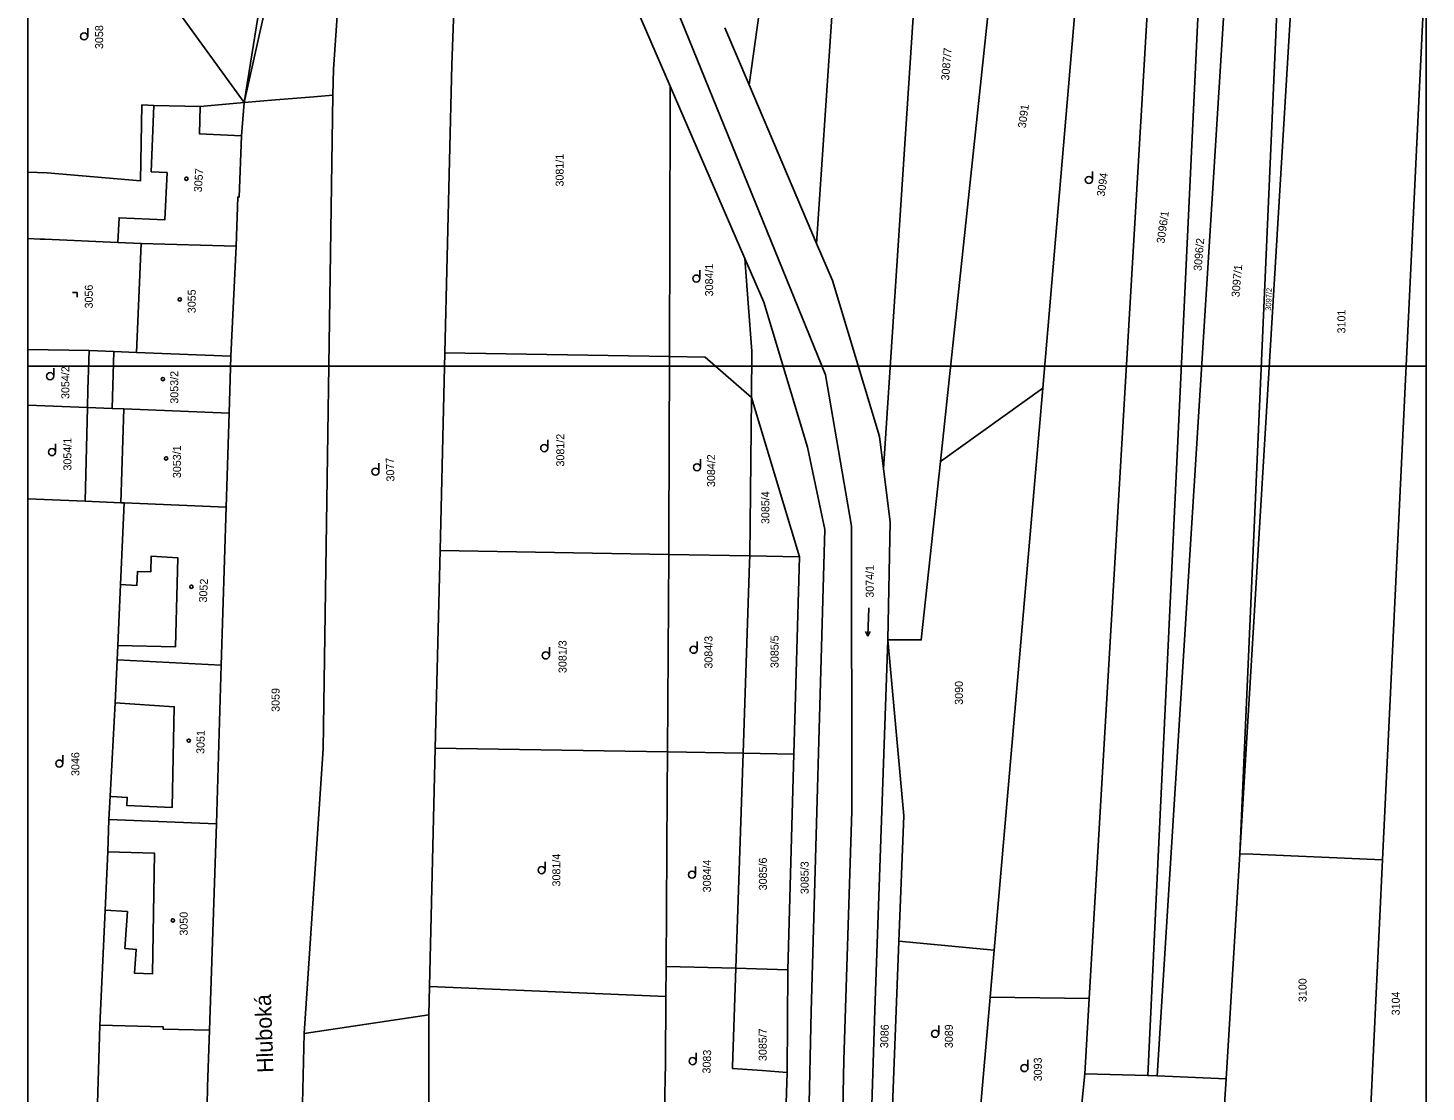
# Model space of a CAD drawing. Extents: x -534410 to -534262, y -1190162 to -1189584.
# Drawn here: x -534410.1 to -534261.6, y -1190081.5 to -1189968.6 of the extents above; entities that cross this region are included whole.
import ezdxf

# ---------------------------------------------------------------- set-up
doc = ezdxf.new("R2010")
doc.units = 0
for name, color, linetype in [('_KN_Povodí_Moravy', 7, 'Continuous'), ('_N_osa', 7, 'Continuous'), ('_rámeček', 7, 'Continuous'), ('_rámeček_mřížka', 7, 'Continuous'), ('_tenka', 7, 'Continuous'), ('Hranice parcel', 7, 'Continuous'), ('Parcelní čísla', 7, 'Continuous'), ('Polygon budovy', 7, 'Continuous'), ('Pop  PČ popisy', 7, 'Continuous'), ('Značky budov', 7, 'Continuous'), ('Značky kultur', 7, 'Continuous')]:
    doc.layers.add(name, color=color, linetype=linetype)

msp = doc.modelspace()

# ---------------------------------------------------------------- linework, layer by layer
at = {"layer": '_KN_Povodí_Moravy'}
for p, q in [((-534351.04, -1189953.66), (-534341.9, -1189974.75)), ((-534333.52, -1189974.6), (-534336.09, -1189968.55)), ((-534341.9, -1189974.75), (-534333.99, -1189993.03)), ((-534326.36, -1189991.44), (-534333.52, -1189974.6))]:
    msp.add_line(p, q, dxfattribs=at)
for points in [[(-534319.25, -1190015.38), (-534319.67, -1190011.96), (-534324.68, -1189995.39), (-534326.36, -1189991.44)], [(-534333.99, -1189993.03), (-534331.98, -1189997.67), (-534327.34, -1190013.08), (-534325.48, -1190021.81), (-534326.93, -1190073), (-534328.13, -1190128.3), (-534328.71, -1190131.86)], [(-534318.8, -1190033.53), (-534318.55, -1190021), (-534319.25, -1190015.38)], [(-534322.11, -1190134.26), (-534321.95, -1190128.7), (-534320.16, -1190072.85), (-534318.8, -1190033.53)]]:
    msp.add_lwpolyline(points, dxfattribs=at)
at = {"layer": '_N_osa'}
msp.add_lwpolyline([(-534327.36, -1190134.6), (-534324.33, -1190120.41), (-534323.46, -1190078.16), (-534322.63, -1190051.74), (-534322.66, -1190021.45), (-534325.42, -1190005.39), (-534346.1, -1189954.57), (-534347.89, -1189950.33)], dxfattribs=at)
at = {"layer": '_rámeček'}
msp.add_line((-534410.13, -1189584.47), (-534410.13, -1190161.97), dxfattribs=at)
msp.add_lwpolyline([(-534410.13, -1190161.97), (-534261.63, -1190161.97), (-534261.63, -1189584.47)], dxfattribs=at)
for points in [[(-534410.13, -1189899.47), (-534261.63, -1189899.47), (-534261.63, -1190004.47), (-534410.13, -1190004.47)], [(-534410.13, -1190004.47), (-534261.63, -1190004.47), (-534261.63, -1190109.47), (-534410.13, -1190109.47)]]:
    msp.add_lwpolyline(points, close=True, dxfattribs=at)
at = {"layer": '_rámeček_mřížka'}
for p, q in [((-534410.13, -1189584.47), (-534410.13, -1190161.97)), ((-534407.13, -1190004.47), (-534410.13, -1190004.47)), ((-534264.63, -1190004.47), (-534261.63, -1190004.47))]:
    msp.add_line(p, q, dxfattribs=at)
msp.add_lwpolyline([(-534410.13, -1190161.97), (-534261.63, -1190161.97), (-534261.63, -1189584.47)], dxfattribs=at)
at = {"layer": '_tenka'}
for p, q in [((-534320.8, -1190030.14), (-534320.93, -1190033.14)), ((-534320.93, -1190033.14), (-534321.16, -1190032.64)), ((-534320.93, -1190033.14), (-534320.66, -1190032.66))]:
    msp.add_line(p, q, dxfattribs=at)
at = {"layer": 'Hranice parcel'}
for p, q in [((-534326.36, -1189991.44), (-534323.33, -1189946.13)), ((-534319.25, -1190015.38), (-534314.72, -1189945.99)), ((-534313.21, -1190014.59), (-534305.87, -1189945.8)), ((-534302.34, -1190006.82), (-534297.16, -1189946.38)), ((-534290.08, -1189946.94), (-534297.41, -1190071.61)), ((-534291.17, -1190079.8), (-534284.92, -1189947.42)), ((-534290.2, -1190079.83), (-534281.9, -1189947.69)), ((-534281.42, -1190056.27), (-534276.65, -1189947.93)), ((-534281.42, -1190056.27), (-534274.89, -1189948.14)), ((-534351.04, -1189953.66), (-534341.9, -1189974.75)), ((-534261.63, -1189960.81), (-534266.24, -1190056.9)), ((-534396.36, -1189963.8), (-534387.17, -1189976.47)), ((-534384.28, -1189963.65), (-534387.17, -1189976.47)), ((-534387.17, -1189976.47), (-534385.09, -1189963.71)), ((-534333.52, -1189974.6), (-534336.09, -1189968.55)), ((-534341.9, -1189974.75), (-534333.99, -1189993.03)), ((-534326.36, -1189991.44), (-534333.52, -1189974.6)), ((-534388.01, -1189991.75), (-534387.85, -1189986.52)), ((-534398.09, -1189991.44), (-534398.61, -1190003.03)), ((-534388.01, -1189991.75), (-534398.09, -1189991.44)), ((-534388.57, -1190003.43), (-534388.01, -1189991.75)), ((-534410.13, -1190002.69), (-534403.61, -1190002.82)), ((-534398.61, -1190003.03), (-534388.57, -1190003.43)), ((-534366.35, -1190024.04), (-534365.84, -1190003.05)), ((-534365.84, -1190003.05), (-534341.99, -1190003.45)), ((-534388.57, -1190003.43), (-534388.75, -1190009.46)), ((-534302.34, -1190006.82), (-534313.21, -1190014.59)), ((-534307.49, -1190066.49), (-534302.34, -1190006.82)), ((-534403.8, -1190008.85), (-534410.13, -1190008.6)), ((-534403.8, -1190008.85), (-534404.06, -1190018.82)), ((-534333.46, -1190024.63), (-534333.29, -1190007.81)), ((-534333.29, -1190007.81), (-534328.17, -1190024.72)), ((-534388.75, -1190009.46), (-534389.06, -1190019.44)), ((-534404.06, -1190018.82), (-534410.13, -1190018.57)), ((-534389.06, -1190019.44), (-534399.91, -1190018.99)), ((-534389.59, -1190036.21), (-534389.06, -1190019.44)), ((-534366.87, -1190045.04), (-534366.35, -1190024.04)), ((-534366.35, -1190024.04), (-534342.06, -1190024.47)), ((-534342.19, -1190045.44), (-534342.06, -1190024.47)), ((-534342.06, -1190024.47), (-534333.46, -1190024.63)), ((-534333.46, -1190024.63), (-534328.17, -1190024.72)), ((-534328.17, -1190024.72), (-534328.79, -1190045.66)), ((-534389.59, -1190036.21), (-534400.65, -1190035.66)), ((-534390.11, -1190053.08), (-534389.59, -1190036.21)), ((-534367.49, -1190070.35), (-534366.87, -1190045.04)), ((-534366.87, -1190045.04), (-534342.19, -1190045.44)), ((-534342.19, -1190045.44), (-534334.16, -1190045.57)), ((-534334.93, -1190068.41), (-534334.16, -1190045.57)), ((-534334.16, -1190045.57), (-534328.79, -1190045.66)), ((-534328.79, -1190045.66), (-534329.41, -1190068.56)), ((-534390.11, -1190053.08), (-534401.52, -1190052.62)), ((-534390.83, -1190074.99), (-534390.11, -1190053.08)), ((-534282.87, -1190080.13), (-534281.42, -1190056.27)), ((-534266.24, -1190056.9), (-534267.52, -1190083.79)), ((-534318.39, -1190085.1), (-534317.63, -1190065.52)), ((-534307.49, -1190066.49), (-534317.63, -1190065.52)), ((-534307.92, -1190071.47), (-534307.49, -1190066.49)), ((-534342.35, -1190068.22), (-534342.37, -1190071.42)), ((-534334.93, -1190068.41), (-534342.35, -1190068.22)), ((-534334.93, -1190068.41), (-534329.41, -1190068.56)), ((-534329.41, -1190068.56), (-534329.49, -1190079.46)), ((-534367.56, -1190073.35), (-534367.49, -1190070.35)), ((-534342.37, -1190071.42), (-534367.49, -1190070.35)), ((-534309.15, -1190085.72), (-534307.92, -1190071.47)), ((-534297.41, -1190071.61), (-534307.92, -1190071.47)), ((-534297.88, -1190079.61), (-534297.41, -1190071.61)), ((-534367.56, -1190073.35), (-534380.79, -1190075.34)), ((-534329.74, -1190087.07), (-534329.49, -1190079.46)), ((-534298.53, -1190086.06), (-534297.88, -1190079.61)), ((-534291.17, -1190079.8), (-534297.88, -1190079.61)), ((-534290.2, -1190079.83), (-534291.17, -1190079.8)), ((-534282.87, -1190080.13), (-534290.2, -1190079.83)), ((-534283.03, -1190082.87), (-534282.87, -1190080.13))]:
    msp.add_line(p, q, dxfattribs=at)
for points in [[(-534333.52, -1189974.6), (-534331.59, -1189960.61), (-534330.81, -1189946.26)], [(-534365.84, -1190003.05), (-534365.09, -1189972.48), (-534364.31, -1189951.16)], [(-534377.74, -1189975.71), (-534377.67, -1189972.94), (-534376.87, -1189961.07), (-534375.31, -1189953.34)], [(-534341.99, -1190003.45), (-534341.91, -1189977.12), (-534341.9, -1189974.75)], [(-534387.17, -1189976.47), (-534391.84, -1189976.92), (-534396.75, -1189976.78), (-534398.02, -1189976.74), (-534398.19, -1189984.8), (-534408.09, -1189983.96), (-534410.13, -1189983.88)], [(-534387.85, -1189986.52), (-534387.71, -1189986.52), (-534387.44, -1189980.01), (-534387.17, -1189976.47)], [(-534387.17, -1189976.47), (-534383.85, -1189976.2), (-534379.76, -1189975.87), (-534377.74, -1189975.71)], [(-534380.79, -1190075.34), (-534378.76, -1190045.09), (-534377.74, -1189975.71)], [(-534398.09, -1189991.44), (-534400.58, -1189991.34), (-534408.35, -1189991), (-534408.84, -1189990.98), (-534410.13, -1189990.91)], [(-534319.25, -1190015.38), (-534319.67, -1190011.96), (-534324.68, -1189995.39), (-534326.36, -1189991.44)], [(-534333.29, -1190007.81), (-534333.24, -1190002.9), (-534333.62, -1189997.8), (-534333.99, -1189993.03)], [(-534333.99, -1189993.03), (-534331.98, -1189997.67), (-534327.34, -1190013.08), (-534325.48, -1190021.81), (-534326.93, -1190073), (-534328.13, -1190128.3), (-534328.71, -1190131.86)], [(-534403.61, -1190002.82), (-534403.75, -1190006.97), (-534403.8, -1190008.85)], [(-534403.61, -1190002.82), (-534400.99, -1190002.93), (-534398.61, -1190003.03)], [(-534342.06, -1190024.47), (-534342.05, -1190022.37), (-534341.99, -1190003.45)], [(-534341.99, -1190003.45), (-534338.18, -1190003.51), (-534333.29, -1190007.81)], [(-534388.75, -1190009.46), (-534399.94, -1190009.01), (-534401.17, -1190008.96), (-534403.8, -1190008.85)], [(-534313.21, -1190014.59), (-534315.24, -1190033.54), (-534318.8, -1190033.53)], [(-534318.8, -1190033.53), (-534318.55, -1190021), (-534319.25, -1190015.38)], [(-534399.91, -1190018.99), (-534400.27, -1190018.98), (-534404.06, -1190018.82)], [(-534400.65, -1190035.66), (-534400.58, -1190034.14), (-534400.29, -1190027.66), (-534399.91, -1190018.99)], [(-534334.16, -1190045.57), (-534333.47, -1190025.37), (-534333.46, -1190024.63)], [(-534322.11, -1190134.26), (-534321.95, -1190128.7), (-534320.16, -1190072.85), (-534318.8, -1190033.53)], [(-534317.63, -1190065.52), (-534317.11, -1190052.22), (-534318.8, -1190033.53)], [(-534401.52, -1190052.62), (-534401.39, -1190050.15), (-534400.88, -1190040.21), (-534400.65, -1190035.66)], [(-534342.35, -1190068.22), (-534342.22, -1190049.76), (-534342.19, -1190045.44)], [(-534402.48, -1190074.44), (-534401.92, -1190062.24), (-534401.64, -1190056.04), (-534401.52, -1190052.62)], [(-534266.24, -1190056.9), (-534280.03, -1190056.3), (-534281.42, -1190056.27)], [(-534329.49, -1190079.46), (-534332.14, -1190079.27), (-534335.3, -1190079.04), (-534335.29, -1190078.85), (-534334.93, -1190068.41)], [(-534342.57, -1190087.3), (-534342.5, -1190083.48), (-534342.42, -1190078.52), (-534342.37, -1190071.42)], [(-534402.81, -1190084.96), (-534402.74, -1190082.76), (-534402.48, -1190074.44)], [(-534390.83, -1190074.99), (-534395.76, -1190074.86), (-534395.76, -1190074.64), (-534402.48, -1190074.44)], [(-534367.47, -1190102.26), (-534367.55, -1190076.15), (-534367.56, -1190073.35)], [(-534391.6, -1190100.55), (-534391.1, -1190082.99), (-534391.04, -1190081), (-534390.83, -1190074.99)], [(-534381.06, -1190105.11), (-534381.43, -1190102.09), (-534380.79, -1190075.34)]]:
    msp.add_lwpolyline(points, dxfattribs=at)
at = {"layer": 'Polygon budovy'}
for points in [[(-534397.05, -1189983.85), (-534395.35, -1189983.92), (-534395.59, -1189988.94), (-534400.44, -1189988.72), (-534400.58, -1189991.34), (-534398.09, -1189991.44), (-534388.01, -1189991.75), (-534387.85, -1189986.52), (-534387.71, -1189986.52), (-534387.44, -1189980.01), (-534391.9, -1189979.81), (-534391.84, -1189976.92), (-534396.75, -1189976.78)], [(-534398.61, -1190003.03), (-534388.57, -1190003.43), (-534388.01, -1189991.75), (-534398.09, -1189991.44)], [(-534400.99, -1190002.93), (-534401.17, -1190008.96), (-534399.94, -1190009.01), (-534388.75, -1190009.46), (-534388.57, -1190003.43), (-534398.61, -1190003.03)], [(-534399.91, -1190018.99), (-534389.06, -1190019.44), (-534388.75, -1190009.46), (-534399.94, -1190009.01), (-534400.27, -1190018.98)], [(-534400.58, -1190034.14), (-534400.65, -1190035.66), (-534389.59, -1190036.21), (-534389.06, -1190019.44), (-534399.91, -1190018.99), (-534400.29, -1190027.66), (-534398.55, -1190027.75), (-534398.5, -1190026.29), (-534397.07, -1190026.31), (-534397.03, -1190024.64), (-534394.19, -1190024.84), (-534394.44, -1190034.26)], [(-534400.88, -1190040.21), (-534394.59, -1190040.63), (-534394.82, -1190051.34), (-534399.63, -1190051.12), (-534399.58, -1190050.27), (-534401.24, -1190050.16), (-534401.39, -1190050.15), (-534401.52, -1190052.62), (-534390.11, -1190053.08), (-534389.59, -1190036.21), (-534400.65, -1190035.66)], [(-534399.83, -1190066.32), (-534399.57, -1190062.39), (-534401.92, -1190062.24), (-534402.48, -1190074.44), (-534395.76, -1190074.64), (-534395.76, -1190074.86), (-534390.83, -1190074.99), (-534390.11, -1190053.08), (-534401.52, -1190052.62), (-534401.64, -1190056.04), (-534396.67, -1190056.19), (-534396.91, -1190069), (-534398.81, -1190068.92), (-534398.62, -1190066.41)]]:
    msp.add_lwpolyline(points, close=True, dxfattribs=at)
at = {"layer": 'Značky budov'}
for centre in [(-534393.29, -1189984.58), (-534394, -1189997.39), (-534395.79, -1190005.85), (-534395.46, -1190014.27), (-534392.77, -1190027.9), (-534393.04, -1190044.24), (-534394.73, -1190063.32)]:
    msp.add_circle(centre, 0.175, dxfattribs=at)
at = {"layer": 'Značky kultur'}
for p, q in [((-534403.78, -1189969.46), (-534403.78, -1189968.58)), ((-534297.06, -1189984.7), (-534297.06, -1189983.82)), ((-534338.76, -1189995.17), (-534338.76, -1189994.29)), ((-534404.89, -1189996.65), (-534405.39, -1189996.65)), ((-534404.89, -1189997.15), (-534404.89, -1189996.65)), ((-534407.39, -1190005.54), (-534407.39, -1190004.67)), ((-534407.2, -1190013.6), (-534407.2, -1190012.72)), ((-534354.92, -1190013.18), (-534354.92, -1190012.3)), ((-534372.85, -1190015.67), (-534372.85, -1190014.79)), ((-534338.68, -1190015.21), (-534338.68, -1190014.34)), ((-534354.74, -1190035.19), (-534354.74, -1190034.31)), ((-534339.05, -1190034.59), (-534339.05, -1190033.71)), ((-534406.42, -1190046.67), (-534406.42, -1190045.79)), ((-534355.2, -1190057.99), (-534355.2, -1190057.11)), ((-534339.22, -1190058.47), (-534339.22, -1190057.6)), ((-534313.39, -1190075.36), (-534313.39, -1190074.48)), ((-534339.15, -1190078.27), (-534339.15, -1190077.39)), ((-534303.91, -1190079.01), (-534303.91, -1190078.14))]:
    msp.add_line(p, q, dxfattribs=at)
for centre in [(-534404.16, -1189969.46), (-534297.44, -1189984.7), (-534339.13, -1189995.17), (-534407.77, -1190005.54), (-534407.57, -1190013.6), (-534355.29, -1190013.18), (-534339.06, -1190015.21), (-534373.22, -1190015.67), (-534339.43, -1190034.59), (-534355.12, -1190035.19), (-534406.8, -1190046.67), (-534355.57, -1190057.99), (-534339.59, -1190058.47), (-534313.77, -1190075.36), (-534339.53, -1190078.27), (-534304.28, -1190079.01)]:
    msp.add_circle(centre, 0.375, dxfattribs=at)

# ---------------------------------------------------------------- texts
at = {"layer": '_tenka'}
msp.add_text('3074/1', height=0.85, rotation=90, dxfattribs=at).set_placement((-534320.29, -1190029.06))
at = {"layer": 'Parcelní čísla'}
for s, height, rotation, p in [('3058', 0.85, 90, (-534402.14, -1189970.8)), ('3087/7', 0.85, 85, (-534312.3, -1189974.17)), ('3091', 0.85, 82, (-534304.15, -1189979.24)), ('3081/1', 0.85, 90, (-534353.23, -1189985.4)), ('3057', 0.85, 86, (-534391.67, -1189986.03)), ('3094', 0.85, 82, (-534295.77, -1189986.51)), ('3096/1', 0.85, 82, (-534289.42, -1189991.49)), ('3096/2', 0.85, 85, (-534285.48, -1189994.39)), ('3084/1', 0.85, 90, (-534337.35, -1189997.06)), ('3097/1', 0.85, 85, (-534281.45, -1189997.18)), ('3056', 0.85, 90, (-534403.24, -1189998.35)), ('3055', 0.85, 90, (-534392.31, -1189998.85)), ('3097/2', 0.595, 87, (-534278.1, -1189998.61)), ('3101', 0.85, 90, (-534270.19, -1190001)), ('3054/2', 0.85, 90, (-534405.73, -1190007.96)), ('3053/2', 0.85, 90, (-534394.16, -1190008.46)), ('3054/1', 0.85, 90, (-534405.51, -1190015.56)), ('3081/2', 0.85, 90, (-534353.16, -1190015.13)), ('3053/1', 0.85, 90, (-534393.88, -1190016.36)), ('3077', 0.85, 92, (-534371.19, -1190016.71)), ('3084/2', 0.85, 90, (-534337.14, -1190017.31)), ('3085/4', 0.85, 90, (-534331.38, -1190021.24)), ('3052', 0.85, 87, (-534391.13, -1190029.59)), ('3081/3', 0.85, 90, (-534352.92, -1190037.06)), ('3084/3', 0.85, 90, (-534337.42, -1190036.59)), ('3085/5', 0.85, 90, (-534330.4, -1190036.53)), ('3059', 0.85, 90, (-534383.4, -1190041.18)), ('3090', 0.85, 90, (-534310.82, -1190040.43)), ('3051', 0.85, 89, (-534391.39, -1190045.65)), ('3046', 0.85, 90, (-534404.67, -1190047.99)), ('3081/4', 0.85, 90, (-534353.58, -1190059.72)), ('3085/6', 0.85, 90, (-534331.64, -1190060.13)), ('3084/4', 0.85, 90, (-534337.59, -1190060.34)), ('3085/3', 0.85, 90, (-534327.21, -1190060.53)), ('3050', 0.85, 90, (-534393.16, -1190064.94)), ('3100', 0.85, 90, (-534274.32, -1190072)), ('3104', 0.85, 90, (-534264.42, -1190073.41)), ('3086', 0.85, 88, (-534318.77, -1190076.9)), ('3089', 0.85, 90, (-534311.89, -1190076.89)), ('3085/7', 0.85, 90, (-534331.66, -1190078.26)), ('3083', 0.85, 88, (-534337.64, -1190079.6)), ('3093', 0.85, 90, (-534302.44, -1190080.41))]:
    msp.add_text(s, height=height, rotation=rotation, dxfattribs=at).set_placement(p)
at = {"layer": 'Pop  PČ popisy'}
msp.add_text('Hluboká', height=1.7, rotation=92, dxfattribs=at).set_placement((-534384.04, -1190079.48))

doc.saveas('drawing.dxf')
